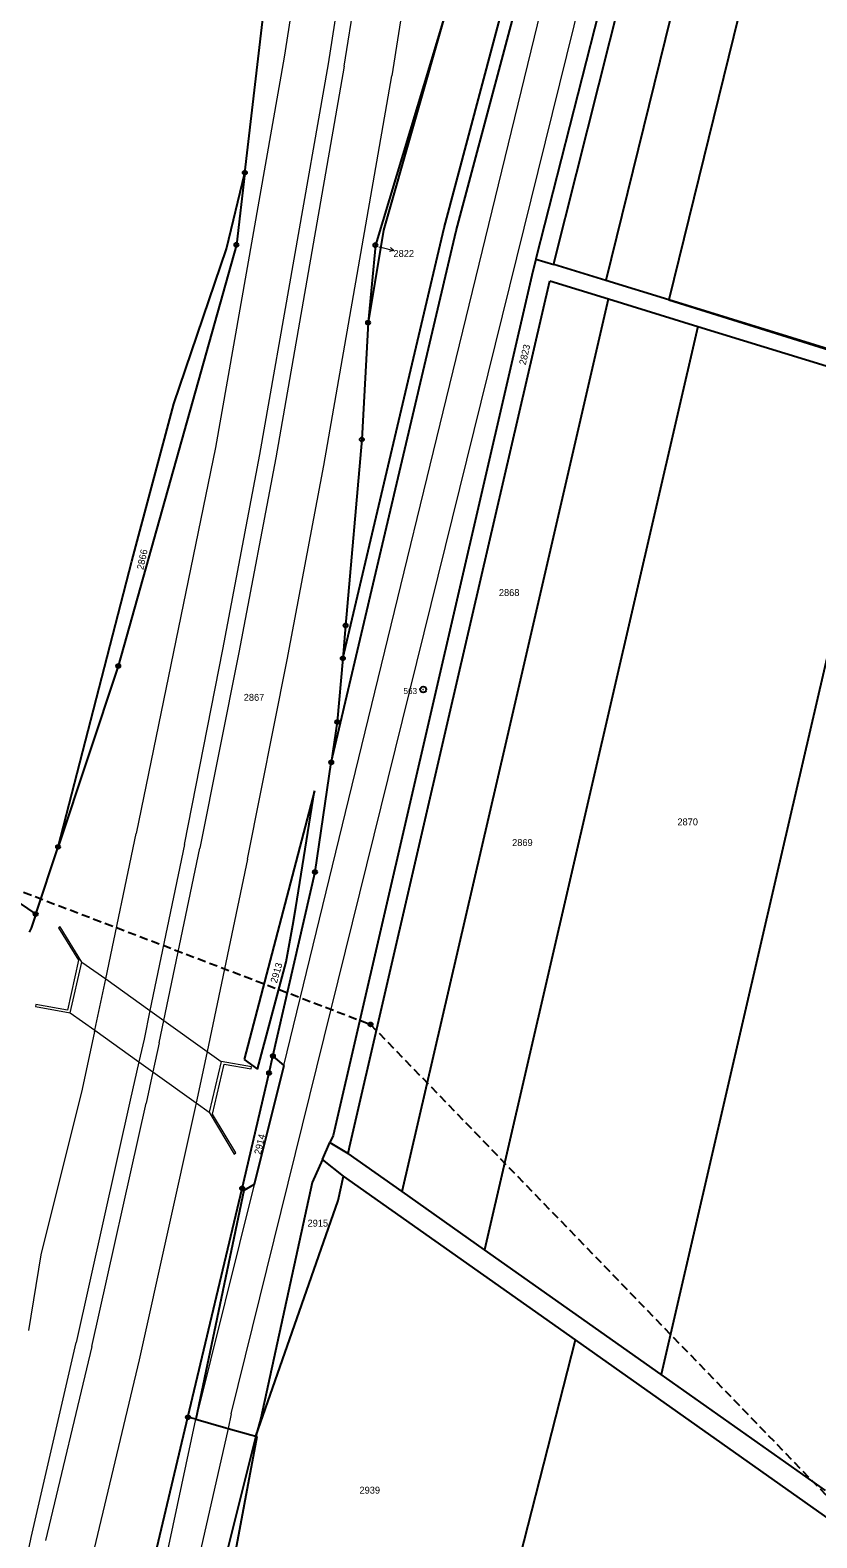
# Model space of a CAD drawing. Extents: x -606517 to -602431, y -1183120 to -1179397.
# Drawn here: x -604821.3 to -604627.6, y -1182125.3 to -1181754.3 of the extents above; entities that cross this region are included whole.
import ezdxf
from ezdxf.enums import TextEntityAlignment as Align

# ---------------------------------------------------------------- set-up
doc = ezdxf.new("R2010")
doc.units = 0
doc.header["$LTSCALE"] = 0.68
doc.linetypes.add('MEDIUM_DASHED', pattern=[4.5, 3, -1.5])
for name, color, linetype, lineweight in [('1', 7, 'Continuous', 25), ('4', 7, 'Continuous', 13), ('6', 7, 'Continuous', 25), ('7', 7, 'Continuous', 13), ('8', 7, 'Continuous', 25)]:
    doc.layers.add(name, color=color, linetype=linetype, lineweight=lineweight)
doc.layers.add('2', color=7, linetype='Continuous')

msp = doc.modelspace()

# ---------------------------------------------------------------- linework, layer by layer
at = {"layer": '1'}
for p, q in [((-604716.39, -1181803.74), (-604667.76, -1181620.8)), ((-604649.64, -1181626.15), (-604696.74, -1181810.26)), ((-604692.29, -1181811.44), (-604645.94, -1181627.2)), ((-604647.32, -1181684.9), (-604679.6, -1181815.95)), ((-604631.81, -1181689.64), (-604664.1, -1181820.72)), ((-604768.46, -1181789.42), (-604758.39, -1181703.49)), ((-604719.4, -1181802.99), (-604695.08, -1181711.47)), ((-604719.22, -1181750.67), (-604736.31, -1181807.24)), ((-604719.22, -1181750.67), (-604734.28, -1181803.54)), ((-604773, -1181808.12), (-604768.46, -1181789.42)), ((-604768.46, -1181789.42), (-604770.54, -1181807.15)), ((-604747.18, -1181934.49), (-604716.39, -1181803.74)), ((-604744.34, -1181908.92), (-604719.4, -1181802.99)), ((-604734.28, -1181803.54), (-604738.12, -1181826.3)), ((-604770.54, -1181807.15), (-604799.63, -1181910.8)), ((-604785.92, -1181846.27), (-604773, -1181808.12)), ((-604736.31, -1181807.24), (-604738.12, -1181826.3)), ((-604696.83, -1181810.65), (-604697.77, -1181814.7)), ((-604696.74, -1181810.26), (-604696.83, -1181810.65)), ((-604696.83, -1181810.65), (-604692.42, -1181812.01)), ((-604692.42, -1181812.01), (-604692.29, -1181811.44)), ((-604679.6, -1181815.95), (-604692.42, -1181812.01)), ((-604697.77, -1181814.7), (-604722.26, -1181920.48)), ((-604718.04, -1181922.67), (-604693.35, -1181816.04)), ((-604693.35, -1181816.04), (-604678.9, -1181820.48)), ((-604664.1, -1181820.72), (-604679.6, -1181815.95)), ((-604704.32, -1181930.29), (-604678.9, -1181820.48)), ((-604678.9, -1181820.48), (-604656.9, -1181827.25)), ((-604664.1, -1181820.72), (-604568.03, -1181850.64)), ((-604541, -1181858.57), (-604664.1, -1181820.72)), ((-604738.12, -1181826.3), (-604739.66, -1181855.06)), ((-604656.9, -1181827.25), (-604683.2, -1181940.82)), ((-604656.9, -1181827.25), (-604609.65, -1181841.77)), ((-604609.65, -1181841.77), (-604637.82, -1181963.43)), ((-604796.31, -1181885.03), (-604785.92, -1181846.27)), ((-604739.66, -1181855.06), (-604743.64, -1181900.82)), ((-604814.45, -1181955.29), (-604796.31, -1181885.03)), ((-604928.6, -1181898.12), (-604819.96, -1181971.83)), ((-604743.64, -1181900.82), (-604744.34, -1181908.92)), ((-604744.34, -1181908.92), (-604745.7, -1181924.55)), ((-604799.63, -1181910.8), (-604814.45, -1181955.29)), ((-604722.26, -1181920.48), (-604746.75, -1182026.27)), ((-604745.7, -1181924.55), (-604747.18, -1181934.49)), ((-604742.69, -1182029.17), (-604718.04, -1181922.67)), ((-604729.75, -1182040.1), (-604704.32, -1181930.29)), ((-604751.18, -1181961.46), (-604747.18, -1181934.49)), ((-604751.31, -1181941.53), (-604768.61, -1182007.61)), ((-604755.92, -1181970.22), (-604751.31, -1181941.53)), ((-604683.2, -1181940.82), (-604709.49, -1182054.4)), ((-604819.96, -1181971.83), (-604814.45, -1181955.29)), ((-604761.54, -1182006.75), (-604751.18, -1181961.46)), ((-604637.82, -1181963.43), (-604665.98, -1182085.09)), ((-604819.96, -1181971.83), (-604821.1, -1181975.25)), ((-604756.61, -1181974.58), (-604755.92, -1181970.22)), ((-604821.1, -1181975.25), (-604821.56, -1181976.25)), ((-604758.32, -1181983.57), (-604756.61, -1181974.58)), ((-604765.35, -1182009.97), (-604758.32, -1181983.57)), ((-604768.61, -1182007.61), (-604765.35, -1182009.97)), ((-604758.86, -1182009.05), (-604766.18, -1182038.35)), ((-604762.49, -1182010.91), (-604761.54, -1182006.75)), ((-604761.54, -1182006.75), (-604758.86, -1182009.05)), ((-604769.12, -1182039.32), (-604762.49, -1182010.91)), ((-604749.38, -1182032.19), (-604747.56, -1182028.05)), ((-604746.75, -1182026.27), (-604747.56, -1182028.05)), ((-604747.56, -1182028.05), (-604743.02, -1182030.74)), ((-604743.02, -1182030.74), (-604742.69, -1182029.17)), ((-604729.75, -1182040.1), (-604743.02, -1182030.74)), ((-604749.38, -1182032.19), (-604751.89, -1182037.85)), ((-604744.19, -1182036.27), (-604749.38, -1182032.19)), ((-604782.46, -1182095.61), (-604769.12, -1182039.32)), ((-604766.18, -1182038.35), (-604768.67, -1182039.84)), ((-604751.89, -1182037.85), (-604764.5, -1182095.88)), ((-604745.45, -1182042.27), (-604744.19, -1182036.27)), ((-604687.02, -1182076.6), (-604744.19, -1182036.27)), ((-604768.67, -1182039.84), (-604780.53, -1182096.1)), ((-604765.78, -1182100.31), (-604745.45, -1182042.27)), ((-604709.49, -1182054.4), (-604729.75, -1182040.1)), ((-604665.98, -1182085.09), (-604709.49, -1182054.4)), ((-604722.94, -1182216.85), (-604687.02, -1182076.6)), ((-604620.95, -1182123.2), (-604687.02, -1182076.6)), ((-604625.46, -1182113.68), (-604665.98, -1182085.09)), ((-604791.72, -1182134.66), (-604782.46, -1182095.61)), ((-604780.53, -1182096.1), (-604782.46, -1182095.61)), ((-604780.53, -1182096.1), (-604773.11, -1182098.22)), ((-604773.11, -1182098.22), (-604772.6, -1182098.36)), ((-604772.6, -1182098.36), (-604766.98, -1182099.97)), ((-604764.5, -1182095.88), (-604765.78, -1182100.31)), ((-604765.78, -1182100.31), (-604787.38, -1182186.5)), ((-604765.48, -1182100.4), (-604775.96, -1182156.06)), ((-604766.98, -1182099.97), (-604765.78, -1182100.31)), ((-604765.78, -1182100.31), (-604765.48, -1182100.4))]:
    msp.add_line(p, q, dxfattribs=at)
at = {"layer": '4'}
for p, q in [((-604771.79, -1182094.77), (-604655.37, -1181623.85)), ((-604758.86, -1182009.05), (-604664.39, -1181621.71)), ((-604743.31, -1181664.1), (-604758.8, -1181760.99)), ((-604747.88, -1181762.59), (-604732.59, -1181666.11)), ((-604744.01, -1181763.24), (-604728.69, -1181666.83)), ((-604716.95, -1181669.02), (-604732.28, -1181765.56)), ((-604758.8, -1181760.99), (-604775.65, -1181856.99)), ((-604764.77, -1181858.77), (-604747.88, -1181762.59)), ((-604744.01, -1181763.24), (-604760.85, -1181859.54)), ((-604749.04, -1181861.46), (-604732.28, -1181765.56)), ((-604775.65, -1181856.99), (-604795.19, -1181951.96)), ((-604783.32, -1181954.66), (-604791.82, -1181995.58)), ((-604791.82, -1181995.58), (-604793.28, -1182002.61)), ((-604805.46, -1182000.72), (-604808.55, -1182014.89)), ((-604774.28, -1182008.12), (-604777.26, -1182020.55)), ((-604773.57, -1182008.75), (-604766.89, -1182009.92)), ((-604796.66, -1182017.64), (-604810, -1182077.22)), ((-604806.1, -1182078.19), (-604792.77, -1182018.32)), ((-604780.7, -1182019.44), (-604794.45, -1182081.46)), ((-604777.26, -1182020.55), (-604771.07, -1182030.85)), ((-604766.18, -1182038.35), (-604780.53, -1182096.1)), ((-604806.1, -1182078.19), (-604817.53, -1182125.91)), ((-604794.45, -1182081.46), (-604811.14, -1182151.18)), ((-604788.9, -1182135.4), (-604780.53, -1182096.1))]:
    msp.add_line(p, q, dxfattribs=at)
for points in [[(-604783.32, -1181954.66), (-604773.88, -1181906.76), (-604764.77, -1181858.77)], [(-604760.85, -1181859.54), (-604769.95, -1181907.45), (-604779.54, -1181955.6)], [(-604767.83, -1181958.28), (-604758.05, -1181909.26), (-604749.04, -1181861.46)], [(-604805.46, -1182000.72), (-604805.4, -1182000.42), (-604802.73, -1181987.77), (-604795.19, -1181951.96)], [(-604789.55, -1182003.48), (-604788.41, -1181998.02), (-604779.54, -1181955.6)], [(-604767.83, -1181958.28), (-604777.72, -1182005.66), (-604778.03, -1182007.15)], [(-604808.57, -1181983.61), (-604802.73, -1181987.77), (-604791.82, -1181995.58), (-604788.41, -1181998.02), (-604777.72, -1182005.66), (-604774.28, -1182008.12)], [(-604811.44, -1181996.1), (-604805.4, -1182000.42), (-604794.54, -1182008.19), (-604791.1, -1182010.65), (-604780.45, -1182018.27), (-604777.26, -1182020.55)], [(-604793.28, -1182002.61), (-604794.54, -1182008.19), (-604796.66, -1182017.64)], [(-604789.55, -1182003.48), (-604791.1, -1182010.65), (-604792.77, -1182018.32)], [(-604778.03, -1182007.15), (-604780.45, -1182018.27), (-604780.7, -1182019.44)], [(-604771.07, -1182030.85), (-604770.64, -1182030.59), (-604776.4, -1182021.01), (-604773.57, -1182008.75)], [(-604766.89, -1182009.92), (-604766.8, -1182009.43), (-604774.28, -1182008.12)], [(-604808.55, -1182014.89), (-604818.73, -1182055.62), (-604821.76, -1182074.24)], [(-604823.24, -1182146.24), (-604825.32, -1182145.75), (-604821.1, -1182125.17), (-604810, -1182077.22)], [(-604771.79, -1182094.77), (-604772.6, -1182098.36), (-604781.36, -1182137.03)]]:
    msp.add_lwpolyline(points, dxfattribs=at)
msp.add_lwpolyline([(-604808.57, -1181983.61), (-604813.93, -1181974.97), (-604814.35, -1181975.23), (-604809.45, -1181983.13), (-604812.14, -1181995.47), (-604819.89, -1181994.08), (-604819.97, -1181994.57), (-604811.44, -1181996.1)], close=True, dxfattribs=at)
at = {"layer": '6', "linetype": 'MEDIUM_DASHED'}
for p, q in [((-604825.79, -1181965.35), (-604737.51, -1181998.96)), ((-604737.51, -1181998.96), (-604621.08, -1182119.18))]:
    msp.add_line(p, q, dxfattribs=at)
at = {"layer": '6'}
for radius in [0.5, 0.4, 0.3, 0.2, 0.1]:
    msp.add_circle((-604737.5134, -1181998.9599), radius, dxfattribs=at)
at = {"layer": '7'}
msp.add_line((-604731.748, -1181808.556), (-604732.599, -1181807.828), dxfattribs=at)
msp.add_lwpolyline([(-604735.45, -1181807.63), (-604734.66, -1181807.83), (-604731.748, -1181808.556), (-604732.841, -1181808.8)], dxfattribs=at)
at = {"layer": '8'}
for centre, radius in [((-604768.46, -1181789.4199), 0.5), ((-604768.46, -1181789.4199), 0.0303), ((-604770.54, -1181807.1499), 0.5), ((-604770.54, -1181807.1499), 0.0303), ((-604736.31, -1181807.2399), 0.5), ((-604736.31, -1181807.2399), 0.0303), ((-604738.12, -1181826.2999), 0.5), ((-604738.12, -1181826.2999), 0.0303), ((-604739.66, -1181855.0599), 0.5), ((-604739.66, -1181855.0599), 0.0303), ((-604743.64, -1181900.8199), 0.5), ((-604743.64, -1181900.8199), 0.0303), ((-604744.34, -1181908.9199), 0.5), ((-604744.34, -1181908.9199), 0.0303), ((-604799.63, -1181910.7999), 0.5), ((-604799.63, -1181910.7999), 0.0303), ((-604724.55, -1181916.5698), 0.75), ((-604724.55, -1181916.5698), 0.03), ((-604745.7, -1181924.5499), 0.5), ((-604745.7, -1181924.5499), 0.0303), ((-604747.18, -1181934.4899), 0.5), ((-604747.18, -1181934.4899), 0.0303), ((-604814.45, -1181955.2899), 0.5), ((-604814.45, -1181955.2899), 0.0303), ((-604751.18, -1181961.4599), 0.5), ((-604751.18, -1181961.4599), 0.0303), ((-604819.96, -1181971.8299), 0.5), ((-604819.96, -1181971.8299), 0.0303), ((-604761.54, -1182006.7499), 0.5), ((-604761.54, -1182006.7499), 0.0303), ((-604762.49, -1182010.9099), 0.5), ((-604762.49, -1182010.9099), 0.0303), ((-604769.12, -1182039.3199), 0.5), ((-604769.12, -1182039.3199), 0.0303), ((-604782.46, -1182095.6099), 0.5), ((-604782.46, -1182095.6099), 0.0303)]:
    msp.add_circle(centre, radius, dxfattribs=at)

# ---------------------------------------------------------------- texts
at = {"layer": '2'}
for s, p in [('2822', (-604731.86, -1181810.145)), ('2868', (-604705.91, -1181893.565)), ('2867', (-604768.73, -1181919.345)), ('2870', (-604661.95, -1181949.985)), ('2869', (-604702.65, -1181955.075)), ('2915', (-604753.02, -1182048.715)), ('2939', (-604740.23, -1182114.405))]:
    msp.add_text(s, height=1.7, dxfattribs=at).set_placement(p)
for s, rotation, p in [('2823', 77, (-604699.315, -1181836.825)), ('2866', 78, (-604793.444, -1181887.208)), ('2913', 74, (-604760.581, -1181988.937)), ('2914', 77, (-604764.545, -1182031.095))]:
    msp.add_text(s, height=1.7, rotation=rotation, dxfattribs=at).set_placement(p)
at = {"layer": '8'}
msp.add_text('563', height=1.5, dxfattribs=at).set_placement((-604726.049, -1181917.687), align=Align.RIGHT)

doc.saveas('drawing.dxf')
